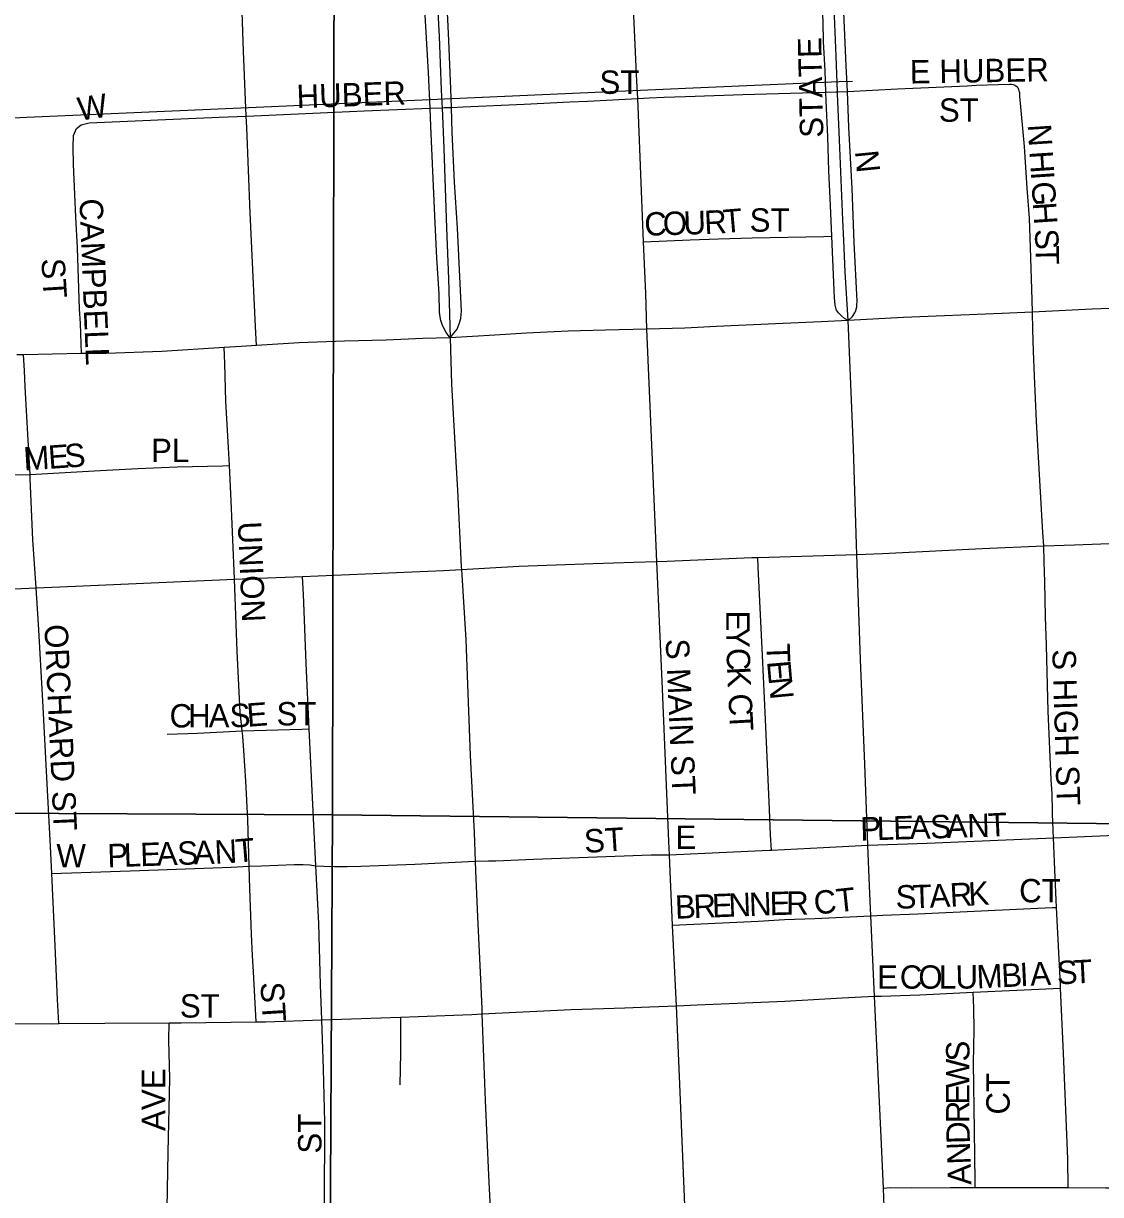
# Model space of a CAD drawing. Extents: x -9.1 to 34, y -3.1 to 22.
# Drawn here: x 5.1008 to 5.5372, y 19.6185 to 20.0929 of the extents above; entities that cross this region are included whole.
import ezdxf

# ---------------------------------------------------------------- set-up
doc = ezdxf.new("R2010")
doc.units = 0
for name, color, linetype in [('GM_X_City_Street', 7, 'Continuous'), ('GM_X_City_Street_Text', 7, 'Continuous'), ('GM_X_Rail_Line', 7, 'Continuous'), ('GM_X_Section', 7, 'Continuous'), ('GM_X_State_Route', 7, 'Continuous')]:
    doc.layers.add(name, color=color, linetype=linetype)

msp = doc.modelspace()

# ---------------------------------------------------------------- linework, layer by layer
at = {"layer": 'GM_X_City_Street'}
for points in [[(5.27419, 20.0589), (5.27394, 20.0664), (5.27371, 20.07288), (5.27312, 20.08605), (5.27234, 20.10294), (5.27174, 20.11983), (5.27056, 20.14143), (5.26956, 20.17169), (5.26858, 20.19388), (5.26759, 20.21784), (5.26737, 20.22316), (5.26707, 20.22611), (5.26633, 20.22978), (5.26516, 20.23286), (5.26428, 20.23506), (5.26212, 20.23884)], [(5.3497, 20.06251), (5.34929, 20.06954), (5.34833, 20.0902), (5.34612, 20.13998), (5.34453, 20.17728), (5.34305, 20.20825), (5.34174, 20.24123)], [(5.26556, 20.05857), (5.26488, 20.07308), (5.2633, 20.10097), (5.26211, 20.12494), (5.26113, 20.1487), (5.26014, 20.17542), (5.26001, 20.17842)], [(5.19111, 20.05537), (5.18999, 20.08168), (5.18905, 20.10951), (5.18815, 20.13574), (5.18772, 20.14817)], [(5.42584, 20.06509), (5.42555, 20.0739), (5.42496, 20.08549), (5.42476, 20.09374), (5.42319, 20.12556), (5.42304, 20.12789)], [(5.43459, 20.06532), (5.43418, 20.07567), (5.43282, 20.10684), (5.43213, 20.12246), (5.43192, 20.12827)], [(5.43459, 20.06532), (5.45496, 20.06642), (5.48315, 20.06768), (5.48692, 20.06788), (5.4957, 20.06818), (5.50034, 20.06835), (5.50108, 20.06826), (5.5018, 20.06814), (5.50242, 20.06789), (5.50286, 20.06767), (5.50348, 20.06717)], [(5.3497, 20.06251), (5.3543, 20.06271), (5.3604, 20.06297), (5.36903, 20.06335), (5.3923, 20.06414), (5.42584, 20.06509)], [(5.42584, 20.06509), (5.42991, 20.0652), (5.43062, 20.06522), (5.43459, 20.06532)], [(5.4283, 20.00667), (5.42773, 20.0191), (5.42714, 20.03324), (5.42674, 20.04699), (5.42595, 20.06153), (5.42584, 20.06509)], [(5.43498, 19.97251), (5.43671, 19.97417), (5.43756, 19.97561), (5.43804, 19.97661), (5.43842, 19.97811), (5.43846, 19.979), (5.43851, 19.98037), (5.43735, 20.00423), (5.43648, 20.026), (5.43525, 20.05089), (5.43459, 20.06532)], [(5.50956, 19.97596), (5.50941, 19.98098), (5.50878, 20.00212), (5.50836, 20.014), (5.5075, 20.02617), (5.50633, 20.0431), (5.50451, 20.0635), (5.50442, 20.06481), (5.50426, 20.06549), (5.50401, 20.06624), (5.50382, 20.06673), (5.50348, 20.06717)], [(5.19111, 20.05537), (5.1973, 20.05562), (5.23879, 20.05755), (5.26556, 20.05857)], [(5.26556, 20.05857), (5.2704, 20.05875), (5.2714, 20.05879), (5.27419, 20.0589)], [(5.27365, 19.96559), (5.27206, 19.96774), (5.27063, 19.97051), (5.26989, 19.97263), (5.26959, 19.97407), (5.2694, 19.9759), (5.26922, 19.98331), (5.26823, 19.99785), (5.26745, 20.01494), (5.26587, 20.05127), (5.26556, 20.05857)], [(5.27365, 19.96559), (5.27521, 19.9674), (5.27653, 19.96902), (5.2775, 19.97158), (5.27797, 19.9734), (5.27814, 19.97494), (5.27831, 19.9764), (5.2766, 20.00997), (5.27549, 20.02863), (5.27451, 20.04892), (5.27419, 20.0589)], [(5.27419, 20.0589), (5.27898, 20.05908), (5.30368, 20.06026), (5.32223, 20.06117), (5.32938, 20.06139), (5.3497, 20.06251)], [(5.35198, 20.00442), (5.35121, 20.02493), (5.34993, 20.05592), (5.3497, 20.06251)], [(5.12231, 20.05028), (5.12424, 20.05183), (5.12738, 20.05262), (5.18008, 20.05494), (5.19111, 20.05537)], [(5.19522, 19.96246), (5.19481, 19.97013), (5.19268, 20.01617), (5.19134, 20.05077), (5.19111, 20.05537)], [(5.12429, 19.95918), (5.12395, 19.97131), (5.12357, 19.97729), (5.12268, 20.00194), (5.12204, 20.01448), (5.1216, 20.02356), (5.1211, 20.03592), (5.1209, 20.04279), (5.1211, 20.04751), (5.12231, 20.05028)], [(5.35198, 20.00442), (5.37098, 20.00527), (5.38234, 20.00565), (5.39605, 20.00611), (5.42506, 20.00661), (5.4283, 20.00667)], [(5.43498, 19.97251), (5.4334, 19.97342), (5.43223, 19.9744), (5.43101, 19.97561), (5.43021, 19.97679), (5.43012, 19.97716), (5.42969, 19.97878), (5.42943, 19.98175), (5.42926, 19.98488), (5.42858, 20.0004), (5.4283, 20.00667)], [(5.35332, 19.96912), (5.35295, 19.9835), (5.35198, 20.00442)], [(5.51415, 19.88125), (5.51375, 19.88673), (5.51179, 19.92192), (5.51124, 19.93179), (5.51041, 19.95018), (5.50996, 19.96011), (5.50974, 19.96892), (5.50956, 19.97596)], [(5.3574, 19.87495), (5.35546, 19.91914), (5.35332, 19.96912)], [(5.10347, 19.91014), (5.10277, 19.92404), (5.10155, 19.94574), (5.10119, 19.95233), (5.10086, 19.95871)], [(5.18423, 19.91384), (5.18386, 19.92116), (5.18285, 19.93976), (5.18234, 19.95525), (5.18212, 19.9616)], [(5.10347, 19.91014), (5.12942, 19.91164), (5.1472, 19.91256), (5.16304, 19.91324), (5.18165, 19.91376), (5.18423, 19.91384)], [(5.18634, 19.86778), (5.18619, 19.87118), (5.18495, 19.89954), (5.18423, 19.91384)], [(4.99274, 19.90598), (5.00021, 19.90641), (5.01245, 19.90712), (5.03697, 19.90804), (5.08306, 19.90961), (5.09523, 19.90999), (5.10347, 19.91014)], [(5.10596, 19.86424), (5.10465, 19.88367), (5.10351, 19.90853), (5.10347, 19.91014)], [(5.51812, 19.76306), (5.51773, 19.77255), (5.51764, 19.77397), (5.51755, 19.78078), (5.51717, 19.78663), (5.51598, 19.81427), (5.51536, 19.8355), (5.51522, 19.84106), (5.51491, 19.85247), (5.51453, 19.86671), (5.51432, 19.87485), (5.51415, 19.88125)], [(5.36253, 19.75617), (5.36228, 19.76147), (5.35967, 19.82331), (5.3574, 19.87495)], [(5.40386, 19.75807), (5.40351, 19.76418), (5.40305, 19.77453), (5.40142, 19.81099), (5.40027, 19.83691), (5.39851, 19.87268), (5.39831, 19.87663)], [(5.21651, 19.80717), (5.21539, 19.83356), (5.21434, 19.85833), (5.21422, 19.86143), (5.21393, 19.86893)], [(5.11226, 19.74855), (5.11175, 19.75955), (5.11032, 19.7875), (5.10867, 19.8185), (5.10694, 19.84955), (5.10596, 19.86424)], [(5.18946, 19.80629), (5.18913, 19.80885), (5.18859, 19.81379), (5.18741, 19.83858), (5.18634, 19.86778)], [(5.18946, 19.80629), (5.21364, 19.80708), (5.21651, 19.80717)], [(5.21925, 19.75172), (5.21859, 19.76544), (5.21651, 19.80717)], [(5.15908, 19.80499), (5.17129, 19.80542), (5.18939, 19.80629), (5.18946, 19.80629)], [(5.19232, 19.75149), (5.19166, 19.77045), (5.1909, 19.78602), (5.19013, 19.79844), (5.18973, 19.80414), (5.18946, 19.80629)], [(5.51812, 19.76306), (5.53065, 19.76359), (5.58323, 19.76587), (5.58912, 19.76609), (5.59162, 19.76618)], [(5.40386, 19.75807), (5.42489, 19.75904), (5.4429, 19.75998)], [(5.4429, 19.75998), (5.46693, 19.76088), (5.49554, 19.76204), (5.51496, 19.76288), (5.51812, 19.76306)], [(5.51939, 19.73484), (5.51867, 19.75001), (5.51812, 19.76306)], [(5.28382, 19.75362), (5.28918, 19.75369), (5.29224, 19.75374), (5.30749, 19.75435), (5.32579, 19.755), (5.35506, 19.75614), (5.36253, 19.75617)], [(5.36253, 19.75617), (5.37104, 19.75656), (5.40303, 19.75804), (5.40386, 19.75807)], [(5.36379, 19.72762), (5.36284, 19.74932), (5.36253, 19.75617)], [(5.11226, 19.74855), (5.14791, 19.74983), (5.18493, 19.75115), (5.19232, 19.75149)], [(5.19232, 19.75149), (5.19721, 19.75172), (5.2105, 19.75225), (5.21414, 19.75222), (5.2169, 19.75203), (5.21925, 19.75172)], [(5.19504, 19.68842), (5.19405, 19.70876), (5.19361, 19.71532), (5.19321, 19.72404), (5.19251, 19.74253), (5.19232, 19.75149)], [(5.21925, 19.75172), (5.22237, 19.7515), (5.22688, 19.7514), (5.23201, 19.7514), (5.23745, 19.75151), (5.2594, 19.75229), (5.28382, 19.75362)], [(5.2217, 19.68928), (5.2212, 19.70351), (5.22043, 19.72826), (5.21925, 19.75172)], [(5.11513, 19.68774), (5.11466, 19.69752), (5.11361, 19.71921), (5.11226, 19.74855)], [(5.36379, 19.72762), (5.36658, 19.72775), (5.3984, 19.72921), (5.40917, 19.72991), (5.42145, 19.73032), (5.44411, 19.7314)], [(5.44411, 19.7314), (5.44898, 19.73168), (5.46309, 19.73223), (5.4916, 19.73357), (5.51761, 19.73476), (5.51939, 19.73484)], [(5.52094, 19.70212), (5.52088, 19.70364), (5.51939, 19.73484)], [(5.36535, 19.69497), (5.36379, 19.72762)], [(5.44564, 19.69885), (5.44828, 19.69893), (5.46392, 19.69941), (5.48559, 19.70048)], [(5.48559, 19.70048), (5.52094, 19.70212)], [(5.48633, 19.62141), (5.48633, 19.62381), (5.48606, 19.64446), (5.48572, 19.6717), (5.48595, 19.6852), (5.48583, 19.69397), (5.48559, 19.70048)], [(5.5241, 19.62132), (5.52398, 19.63286), (5.52219, 19.67581), (5.52094, 19.70212)], [(5.28658, 19.69171), (5.32275, 19.69341), (5.34445, 19.69421), (5.35455, 19.69456), (5.36535, 19.69497)], [(5.11513, 19.68774), (5.13372, 19.688), (5.15982, 19.6881)], [(5.1567, 19.43064), (5.1567, 19.43948), (5.15671, 19.44257), (5.15661, 19.45491), (5.15718, 19.48867), (5.1577, 19.51924), (5.15814, 19.55026), (5.15838, 19.5781), (5.1589, 19.60544), (5.1595, 19.63556), (5.16007, 19.66558), (5.15974, 19.68101), (5.15982, 19.6881)], [(5.15982, 19.6881), (5.1647, 19.68811), (5.19504, 19.68842)], [(5.19504, 19.68842), (5.19881, 19.68846), (5.2217, 19.68928)], [(5.22129, 19.48234), (5.22187, 19.50201), (5.22191, 19.52371), (5.22222, 19.56405), (5.22274, 19.61367), (5.22294, 19.6478), (5.22238, 19.66947), (5.2217, 19.68928)], [(5.2217, 19.68928), (5.25353, 19.69043)], [(5.25353, 19.69043), (5.25354, 19.68694), (5.25358, 19.67584), (5.25324, 19.663)], [(5.25353, 19.69043), (5.26077, 19.69068), (5.28241, 19.69151), (5.28658, 19.69171)], [(5.09474, 19.68775), (5.11204, 19.6877), (5.11513, 19.68774)], [(5.44925, 19.62112), (5.45196, 19.62136), (5.46047, 19.62128), (5.47633, 19.62143), (5.48633, 19.62141)], [(5.48633, 19.62141), (5.51814, 19.62134), (5.5241, 19.62132)], [(5.5241, 19.62132), (5.53913, 19.62127), (5.56737, 19.62118), (5.58496, 19.62132), (5.59053, 19.62138), (5.59708, 19.6213)]]:
    msp.add_lwpolyline(points, dxfattribs=at)
at = {"layer": 'GM_X_Rail_Line'}
for points in [[(4.75491, 20.03998), (4.88383, 20.04522), (5.08049, 20.05405), (5.19819, 20.05912), (5.37213, 20.0668), (5.43128, 20.06935)], [(5.43128, 20.06935), (5.4367, 20.06958)]]:
    msp.add_lwpolyline(points, dxfattribs=at)
at = {"layer": 'GM_X_Section'}
for points in [[(4.22892, 20.78268), (5.2279, 20.77322), (5.226, 19.77229), (4.2285, 19.77719)], [(5.2279, 20.77322), (6.2403, 20.76479), (6.2379, 19.76083), (5.226, 19.77229)], [(4.2285, 19.77719), (5.226, 19.77229), (5.22068, 18.771), (4.22542, 18.77097)], [(5.226, 19.77229), (6.2379, 19.76083), (6.22532, 18.76489), (5.22068, 18.771)]]:
    msp.add_lwpolyline(points, close=True, dxfattribs=at)
at = {"layer": 'GM_X_State_Route'}
for points in [[(5.26473, 20.17901), (5.2662, 20.14933), (5.26739, 20.12446), (5.26848, 20.10275), (5.26919, 20.08765), (5.27009, 20.06595), (5.27033, 20.06057), (5.2704, 20.05875), (5.27106, 20.04227), (5.27222, 20.01011), (5.27296, 19.98939), (5.27365, 19.96559)], [(5.43279, 20.01338), (5.43145, 20.04569), (5.43065, 20.06433), (5.43062, 20.06522), (5.43005, 20.07963), (5.42927, 20.09905), (5.42867, 20.11406), (5.42794, 20.12812), (5.42768, 20.13329), (5.42622, 20.16397), (5.42584, 20.17195)], [(5.43498, 19.97251), (5.43375, 19.9923), (5.43313, 20.00504), (5.43279, 20.01338)], [(5.58144, 19.97895), (5.57461, 19.9787), (5.56693, 19.97843), (5.54439, 19.97757), (5.53371, 19.97716), (5.50956, 19.97596), (5.49713, 19.97535), (5.45737, 19.97384), (5.43498, 19.97251)], [(5.43498, 19.97251), (5.42405, 19.97209), (5.40543, 19.97117), (5.38162, 19.97009), (5.36872, 19.9695), (5.35332, 19.96912), (5.33666, 19.9687), (5.32148, 19.96831), (5.30456, 19.96748), (5.29183, 19.96657), (5.27365, 19.96559)], [(5.43845, 19.87782), (5.43828, 19.88187), (5.43707, 19.92083), (5.43498, 19.97251)], [(5.27365, 19.96559), (5.26257, 19.96521), (5.24782, 19.96461), (5.23082, 19.96415), (5.21246, 19.96347), (5.19522, 19.96246), (5.18898, 19.96204), (5.18212, 19.9616), (5.15693, 19.95999), (5.13434, 19.95919), (5.12429, 19.95918), (5.10086, 19.95871), (5.09809, 19.95866)], [(5.27365, 19.96559), (5.27424, 19.94677), (5.27608, 19.91305), (5.27664, 19.90379), (5.27821, 19.87274), (5.27826, 19.87168)], [(5.43845, 19.87782), (5.44879, 19.87814), (5.48925, 19.88022), (5.51415, 19.88125), (5.52659, 19.88176), (5.54796, 19.88257), (5.57164, 19.88358), (5.58561, 19.88409)], [(5.27826, 19.87168), (5.30147, 19.87304), (5.31661, 19.87357), (5.33166, 19.8742), (5.3481, 19.87466), (5.3574, 19.87495), (5.36161, 19.87513), (5.39585, 19.87656), (5.39831, 19.87663), (5.43845, 19.87782)], [(5.44564, 19.69885), (5.44411, 19.7314), (5.44354, 19.74357), (5.4429, 19.75998), (5.44163, 19.79286), (5.43992, 19.83529), (5.43845, 19.87782)], [(4.96708, 19.86003), (4.96844, 19.85993), (4.98007, 19.8599), (4.98913, 19.85984), (4.99547, 19.86005), (5.00153, 19.86024), (5.02807, 19.86123), (5.02924, 19.86127), (5.06928, 19.86271), (5.09104, 19.86356), (5.10596, 19.86424), (5.12191, 19.86496), (5.18634, 19.86778), (5.19618, 19.86822), (5.21393, 19.86893), (5.27092, 19.87124), (5.27826, 19.87168)], [(5.27826, 19.87168), (5.28006, 19.84318), (5.28181, 19.79633), (5.28337, 19.76515), (5.28382, 19.75362), (5.28398, 19.74967), (5.28477, 19.73095), (5.28607, 19.7028), (5.28649, 19.6937)], [(5.36535, 19.69497), (5.37371, 19.69535), (5.40932, 19.69688), (5.43256, 19.69814), (5.44564, 19.69885)], [(5.45868, 19.40028), (5.45866, 19.40286), (5.45863, 19.40561), (5.45611, 19.46243), (5.45539, 19.4795), (5.45429, 19.50575), (5.45208, 19.55229), (5.45181, 19.55598), (5.4506, 19.58347), (5.44961, 19.60975), (5.44925, 19.62112), (5.44834, 19.6417), (5.44564, 19.69885)], [(5.28649, 19.6937), (5.28658, 19.69171), (5.28787, 19.65667), (5.28916, 19.62637), (5.29057, 19.5991), (5.29075, 19.59607), (5.29096, 19.58995), (5.29142, 19.58078), (5.29198, 19.56245), (5.29301, 19.54039)], [(5.37117, 19.54975), (5.37026, 19.57497), (5.3697, 19.59053), (5.36859, 19.61748), (5.36683, 19.66002), (5.36535, 19.69497)]]:
    msp.add_lwpolyline(points, dxfattribs=at)

# ---------------------------------------------------------------- texts
at = {"layer": 'GM_X_City_Street_Text'}
for s, rotation, p in [('STATE', 91.3016, (5.4249, 20.04668)), ('E HUBER', 0.9856, (5.45997, 20.06854)), ('ST', 0, (5.33418, 20.06437)), ('HUBER', 2.0123, (5.21162, 20.05854)), ('W', 8.5224, (5.12351, 20.05344)), ('ST', 0, (5.47168, 20.05308)), ('N', 273.7836, (5.50762, 20.05187)), ('N', 275.7063, (5.43762, 20.0411)), ('H', 273.7836, (5.50834, 20.04105)), ('I', 273.8185, (5.50889, 20.03273)), ('G', 273.7836, (5.50917, 20.02858)), ('CAMPBELL', 272.3219, (5.12346, 20.02181)), ('C', 1.6276, (5.35246, 20.00687)), ('O', 1.6178, (5.35996, 20.00709)), ('U', 1.6154, (5.36829, 20.00732)), ('R', 2.7844, (5.37683, 20.00756)), ('T', 4.8442, (5.38468, 20.00796)), ('ST', 0, (5.39501, 20.00854)), ('H', 273.8171, (5.50972, 20.02026)), ('S', 273.3617, (5.51043, 20.00946)), ('T', 270.9562, (5.51082, 20.00291)), ('ST', 273.5746, (5.10803, 19.99752)), ('M', 3.4669, (5.10107, 19.91182)), ('E', 4.0933, (5.11116, 19.91243)), ('S', 4.0739, (5.11781, 19.91291)), ('PL', 0, (5.15251, 19.9152)), ('UNION', 272.5451, (5.18763, 19.89096)), ('E', 270.0547, (5.3855, 19.85508)), ('ORCHARD ST', 272.6037, (5.10929, 19.84933)), ('Y', 270.7362, (5.38551, 19.84829)), ('S MAIN ST', 272.5248, (5.36096, 19.8435)), ('T', 272.0766, (5.40179, 19.84166)), ('C', 271.5494, (5.38562, 19.83981)), ('S HIGH ST', 271.7079, (5.51762, 19.83932)), ('K', 272.4961, (5.38583, 19.83215)), ('E', 274.9931, (5.40206, 19.83448)), ('N', 275.4423, (5.40265, 19.82776)), ('C', 273.0455, (5.38633, 19.82123)), ('C', 0.0486, (5.16001, 19.8077)), ('H', 0.0437, (5.16751, 19.80771)), ('A', 0.0379, (5.17584, 19.80772)), ('S', 1.764, (5.18449, 19.80773)), ('E', 4.3561, (5.19161, 19.80796)), ('ST', 0, (5.20335, 19.80854)), ('T', 273.1168, (5.38672, 19.81373)), ('P', 1.7216, (5.43996, 19.76187)), ('L', 1.7216, (5.44662, 19.76207)), ('E', 1.7216, (5.45329, 19.76227)), ('A', 1.7052, (5.45995, 19.76247)), ('S', 1.714, (5.46828, 19.76272)), ('A', 1.7172, (5.47494, 19.76292)), ('N', 1.7052, (5.48327, 19.76317)), ('T', 2.7915, (5.4918, 19.76342)), ('ST', 3.5738, (5.32823, 19.75687)), ('E', 0, (5.36501, 19.75853)), ('W', 0, (5.11418, 19.75103)), ('P', 1.9128, (5.13495, 19.75103)), ('L', 1.9522, (5.14162, 19.75126)), ('E', 1.9128, (5.14828, 19.75148)), ('A', 1.9314, (5.15495, 19.75171)), ('S', 1.9522, (5.16328, 19.75199)), ('A', 1.9237, (5.16995, 19.75221)), ('N', 2.8794, (5.17845, 19.7525)), ('T', 4.8818, (5.18713, 19.75294)), ('R', 3.1764, (5.47636, 19.7351)), ('K', 3.1713, (5.48385, 19.73551)), ('CT', 0, (5.50418, 19.73687)), ('R', 2.155, (5.37244, 19.73048)), ('E', 2.1312, (5.37993, 19.73076)), ('N', 2.1453, (5.3866, 19.73101)), ('N', 2.1421, (5.39493, 19.73132)), ('E', 1.6397, (5.40323, 19.73163)), ('R', 0.34, (5.40984, 19.73182)), ('CT', 6.0054, (5.42149, 19.73186)), ('S', 0.2732, (5.45419, 19.73437)), ('T', 1.9272, (5.46115, 19.73441)), ('A', 3.1505, (5.46804, 19.73464)), ('B', 2.1373, (5.36494, 19.7302)), ('M', 2.632, (5.48715, 19.702)), ('B', 2.9268, (5.49719, 19.70245)), ('I', 2.8864, (5.50468, 19.70284)), ('A', 2.9019, (5.50884, 19.70305)), ('S', 2.9037, (5.51966, 19.7036)), ('T', 2.8979, (5.52632, 19.70394)), ('E', 0.0273, (5.44668, 19.70187)), ('C', 0.0178, (5.45585, 19.70188)), ('O', 0.0154, (5.46335, 19.70188)), ('L', 0.0206, (5.47168, 19.70188)), ('U', 0.6462, (5.47846, 19.70189)), ('ST', 273.5746, (5.19679, 19.70437)), ('ST', 0, (5.16418, 19.69021)), ('S', 90, (5.48406, 19.67241)), ('AVE', 90, (5.15823, 19.64426)), ('W', 90, (5.48406, 19.66158)), ('CT', 90, (5.50035, 19.65092)), ('E', 90, (5.48406, 19.65491)), ('R', 90.0729, (5.48407, 19.64742)), ('ST', 90, (5.22156, 19.63509)), ('D', 91.3551, (5.48427, 19.63914)), ('N', 92.1905, (5.48458, 19.63085)), ('A', 92.164, (5.4849, 19.62252))]:
    msp.add_text(s, height=0.00947, rotation=rotation, dxfattribs=at).set_placement(p)

doc.saveas('drawing.dxf')
